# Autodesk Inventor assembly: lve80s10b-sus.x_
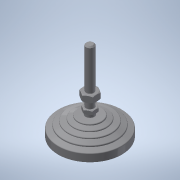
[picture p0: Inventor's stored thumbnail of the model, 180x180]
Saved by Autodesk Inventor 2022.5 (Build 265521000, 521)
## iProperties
Part Number: lve80s10b-sus.x_
Material: 一般
Document SubType Name: Assembly
Designer: ImaoCorp
Sending System: SOLIDWORKS 2017-2017317
MC: AMD64
MC_MODEL: Intel64 Family 6 Model 60 Stepping 3, GenuineIntel
OS: Windows_NT
FRU: Parasolid Version 29.0, build 201,  4-17-2017
FORMAT: text
GUISE: transmit
KEY: lve80s10b-sus
FILE: lve80s10b-sus.x_t
DATE: Mon Jul 01 18:21:46 2019
Author: ImaoCorp
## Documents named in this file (3)
- X:\14_SW2022-Inv2022\00_全2023-1023新製品(TCC)まで\l\lve80s10b-sus\LVE80S10B-SUS.iam
- X:\14_SW2022-Inv2022\00_全2023-1023新製品(TCC)まで\l\lve80s10b-sus\lve80s10b-sus_01.ipt
- X:\14_SW2022-Inv2022\00_全2023-1023新製品(TCC)まで\l\lve80s10b-sus\lve80s10b-sus_02.ipt
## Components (2 placed, 2 different names)
1. lve80s10b-sus_01
2. lve80s10b-sus_02
